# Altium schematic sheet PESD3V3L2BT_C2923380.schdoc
size 127 x 101 mm
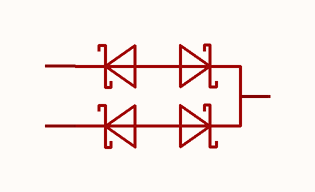
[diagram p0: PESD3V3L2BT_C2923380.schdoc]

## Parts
D?  pesd3v3l2bt_c2923380  [SOT-23-3_L2.9-W1.3-P1.90-LS2.4-BR]  (value not drawn)

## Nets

Not connected (* = marked no-connect by the designer): D? 1 2 3

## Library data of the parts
D? = pesd3v3l2bt_c2923380: 极性:双向;反向截止电压(Vrwm):3.3V;钳位电压:10V;峰值脉冲电流(Ipp):22A;峰值脉冲功率(Ppp):200W;击穿电压:4.4V;; Manufacturer: TECH PUBLIC(台舟); AddInBom: yes; ModelId: c62791f0466c4ae2a892c056b845b0ca; ModelName: SOT-23-3P_L2.9-W1.3-H1.0-LS2.4-P0.95; ModelTransform: 98.425,114.173,0,180,0,0,0.0005,-0.0005,0; Polarity: 双向; Reverse Stand-Off Voltage (Vrwm): 3.3V; Clamping Voltage: 10V; Peak Pulse Current (Ipp): 22A; Peak Pulse Power Dissipation (Ppp): 200W; Voltage - Breakdown: 4.4V; Reverse Leakage Current (Ir): 100nA; Number of Channels: 双路; level of protection: IEC 61000-4-4；IEC 61000-4-5；IEC 61000-4-2; Junction Capacitance: 30pF；17pF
